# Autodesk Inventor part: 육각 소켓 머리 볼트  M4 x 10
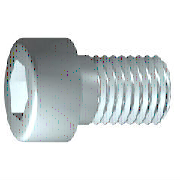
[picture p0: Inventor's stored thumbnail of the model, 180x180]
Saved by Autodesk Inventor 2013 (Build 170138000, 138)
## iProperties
Created: 2012-02
Part Number: 육각 소켓 머리 볼트  M4 x 10
Material: 스테인리스강
Description: 6각 소켓 머리 캡 나사
Document SubType Name: Modeling
Standard: ISO 4762
Designer: mdu-01
Standard Revision: Fourth edition 2004-03-01
Standards Organization: ISO
Language: ko-KR
Size Designation: M4 x 10
Categories: <MemberInstance><Categories><Category DisplayName="조임쇠" InternalName="e4da775c-781d-43d5-af7c-5136215cf5a6" Mnemonic="FSTN"><Category DisplayName="볼트" InternalN
Density: 7.75 g/cm^3
IsCustomPart: 1
Author: mdu-01
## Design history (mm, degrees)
sketch "스케치1"
  geometry: L1 (-1, 0)-(10, 0); L2 (10, 0)-(10, 2); L3 (10, 2)-(1.75, 2); L4 (1.75, 2)-(1.32, 2); L5 (1.32, 2)-(0, 2); L6 (0, 2)-(0, 3.5); L7 (0, 3.5)-(-4, 3.5); L8 (-4, 3.5)-(-4, 1.732); L9 (-4, 1.732)-(-2, 1.732); L10 (-2, 1.732)-(-1, 0); L11 (-6.8, 0)-(12.8, 0) reference; L12 (0, -0.7)-(0, 4.2) reference; L13 (1.75, 2)-(0, 2)
  constraints: 22 end point, 6 parallel, 2 collinear, 2 perpendicular, 1 horizontal, 1 point on line
  dimensions: "d1" = 8.25 distance from line of L3.end L2 (= GEL); "d2" = 0.42952 distance of L4.end L3.end (computed from GAL); "d3" = 4 distance between parallel lines of L8 L6 (= KOH); "d4" = 2 distance of L8.end L9.end (= INTI); "d5" = 60 deg angle of L10 L1; "d6" = 4 diameter of L3 L1 (= GD); "d7" = 4 diameter of L5 L1 (= BDM); "d8" = 3.4641 diameter of L9 L1 (= 1.1547 x SW); "d9" = 7 diameter of L7 L1 (= KOD); "d26" = 10 distance between parallel lines of L12 L2 (= NLG)
revolve "본체" sketch "스케치1" stored, may be unused: angle "d10" = 90 deg
sketch "스케치2"
  geometry: L1 (0, -4.9)-(0, 4.9) reference; L2 (-4.9, 0)-(4.9, 0) reference; L3 (1.732, 0)-(0.866, -1.5); L4 (0.866, -1.5)-(-0.866, -1.5); L5 (-0.866, -1.5)-(-1.732, 0); L6 (-1.732, 0)-(-0.866, 1.5); L7 (-0.866, 1.5)-(0.866, 1.5); L8 (0.866, 1.5)-(1.732, 0); 2 further points
  constraints: 12 end point, 1 coincident, 1 horizontal alignment, 1 point on line, 12 other
extrude "슬롯" join sketch "스케치2" stored distance "d11" = 10; taper "d12" = 0 deg
workplane "Work Plane1"
fillet "Fillet2" dims "d30" = 0.1 (= R)
body "Solid1"
fillet "모깎기1" dims "d17" = 0.4 (= RR)
feature "스레드" dims "d13" = 8.25 (= GEL), "d14" = 0
chamfer "모따기1" distance "d15" = 0.42941 (= -0.5 x SPD + 0.5 x GD); stored, may be unused: second distance "d16" = 0.42941 (= GUL), angle "d27" = 45 deg
other parameters: "GD" = 4 [user parameter; used in 2 equation terms], "NLG" = 10 [user parameter; used in 1 equation term], "GEL" = 8.25 [user parameter; used in 2 equation terms], "KOD" = 7 [user parameter; used in 1 equation term], "KOH" = 4 [user parameter; used in 1 equation term], "INTI" = 2 [user parameter; used in 1 equation term], "GAL" = 0.42941 (= 0.61345 x PTC) [user parameter; used in 1 equation term], "GUL" = 0.42941 (= 0.61345 x PTC) [user parameter; used in 1 equation term], "BDM" = 4 (= NND) [user parameter; used in 1 equation term], "SW" = 3 [user parameter; used in 2 equation terms], "RR" = 0.4 [user parameter; used in 1 equation term], "SPD" = 3.14117 (= NND - 1.2269 x PTC) [user parameter; used in 1 equation term], "d19" = 0, "d28" = 0, "d29" = 0, "R" = 0.1 [user parameter; used in 1 equation term], "TOA" = 30 deg [user parameter], "GD1" = 3.14117 (= THREADDIA - 1.2269 x PTC) [user parameter], "THREADDIA" = 4 [user parameter; used in 1 equation term], "FAWI" = 45 deg [user parameter], "TPU" = 14.28571 (computed from PTC) [user parameter], "PTC" = 0.7 [user parameter; used in 5 equation terms], "NND" = 4 [user parameter; used in 2 equation terms], "E0" = 3.465 (= 1.155 x SW) [user parameter]
